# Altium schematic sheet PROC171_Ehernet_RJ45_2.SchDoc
size 431 x 279 mm; Date: Not shown in title block; ApprovedBy: Not shown in title block; CheckedBy: Not shown in title block; Author: Not shown in title block; CompanyName: Not shown in title block; Engineer: Not shown in title block; Organization: Not shown in title block; Address1: Not shown in title block; Address2: Not shown in title block; Address3: Not shown in title block; Address4: Not shown in title block; DocumentNumber: 20; Revision: Use project parameter SCH_Rev; SheetNumber: 20; SheetTotal: 27; PageSetup: Record=PageOptions¦CenterHorizontal=True¦CenterVertical=True¦PrintScale=1.00¦XCorrection=1.00¦YCorrection=1.00¦PrintKind=0¦BorderSize=5000000¦LeftOffset=0¦BottomOffset=0¦Orientation=2¦PaperLength=1000¦PaperWidth=1000¦Scale=100¦PaperSource=15¦PrintQuality=600¦MediaType=1¦DitherType=10¦PaperKind=Letter¦PrintScaleMode=1
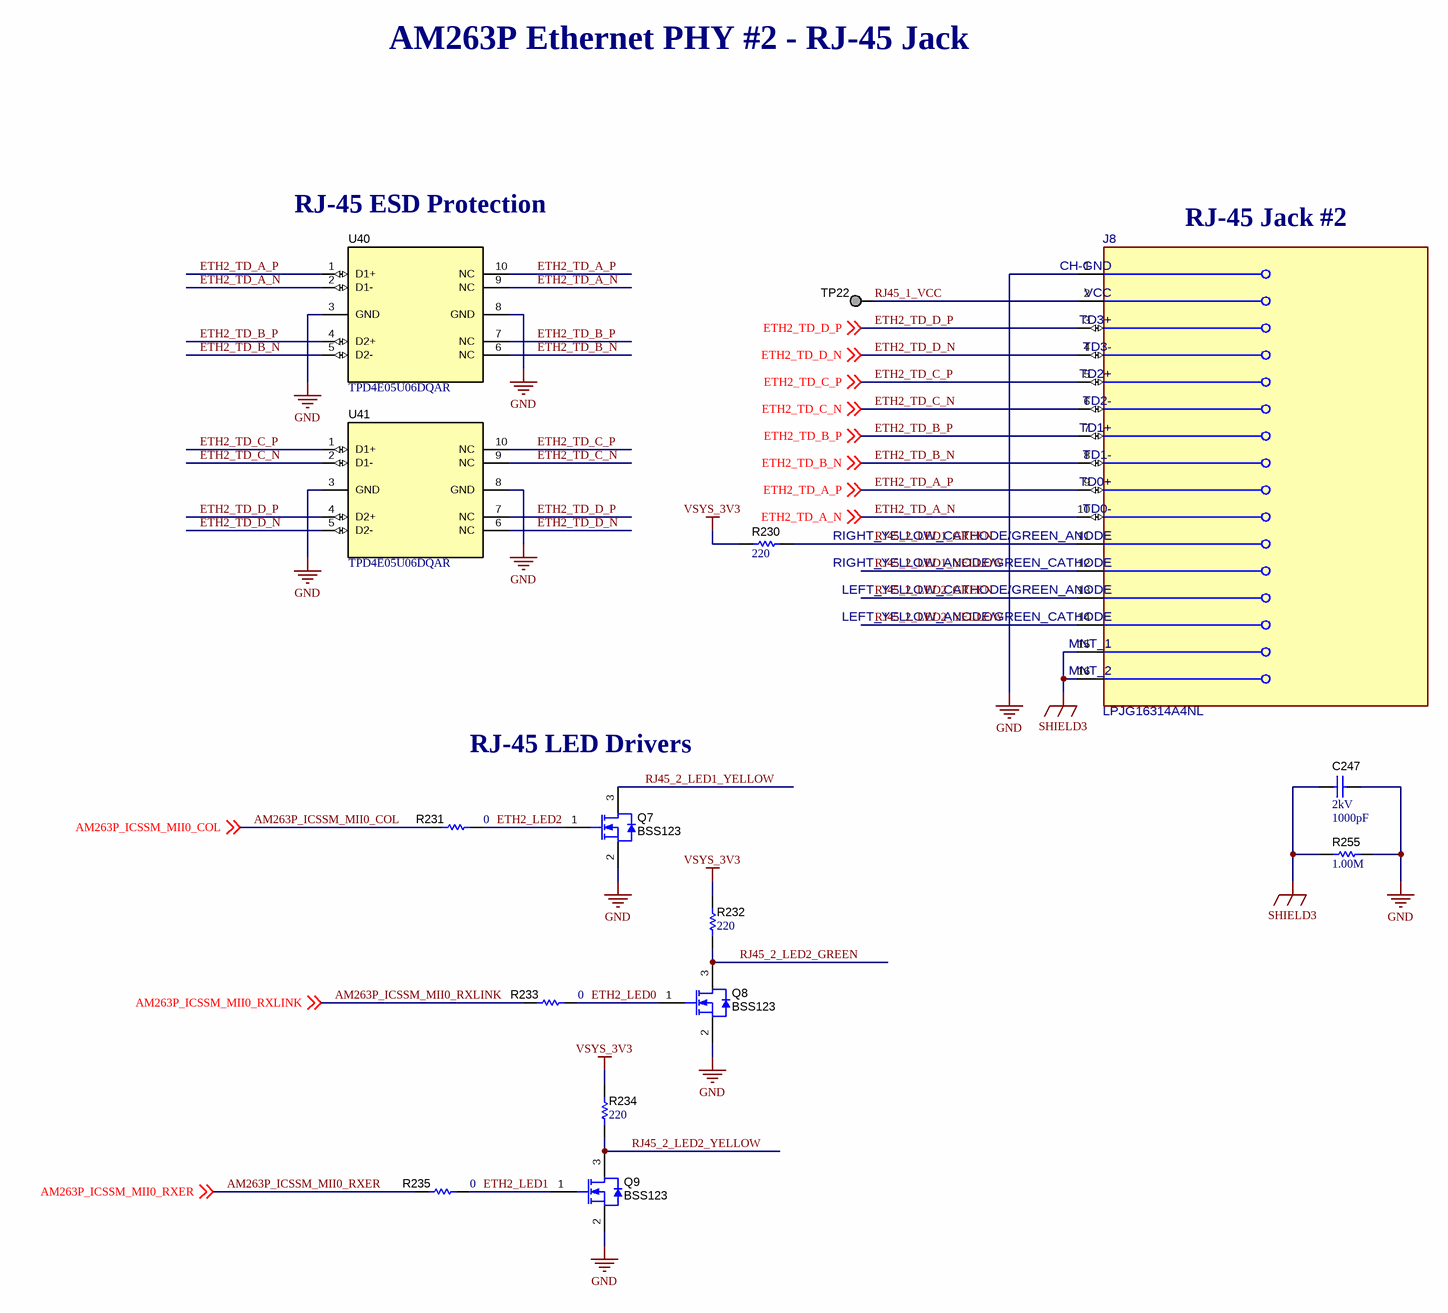
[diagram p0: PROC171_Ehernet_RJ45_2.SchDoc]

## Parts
C247  VDC_V: 2kV  ValueDisplayed: 1000pF  [1808]  (hidden comment: GR442QR73D102KW01L)
J8  LPJG16314A4NL  [FP-LPJG16314A4NL_CONN_RJ45-MFG]
Q7  BSS123  [SOT-23]
Q8  BSS123  [SOT-23]
Q9  BSS123  [SOT-23]
R230  ValueDisplayed: 220  [0402]  (hidden comment: CRCW0402220RJNED)
R231  ValueDisplayed: 0  [0402L]  (hidden comment: ERJ-2GE0R00X)
R232  ValueDisplayed: 220  [0402]  (hidden comment: CRCW0402220RJNED)
R233  ValueDisplayed: 0  [0402L]  (hidden comment: ERJ-2GE0R00X)
R234  ValueDisplayed: 220  [0402]  (hidden comment: CRCW0402220RJNED)
R235  ValueDisplayed: 0  [0402L]  (hidden comment: ERJ-2GE0R00X)
R255  ValueDisplayed: 1.00M  [0805_HV]  (hidden comment: ERJ-6ENF1004V)
TP22  TESTPOINT  [TP_25MIL-SMT]  (value not drawn)  (no BOM)
U40  TPD4E05U06DQAR  [DQA0010A]
U41  TPD4E05U06DQAR  [DQA0010A]

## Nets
GND: C247.1 J8.1(CH-GND) Q7.2(S) Q8.2(S) Q9.2(S) R255.2 U40.3(GND) U40.8(GND) U41.3(GND) U41.8(GND)
SHIELD3: C247.2 J8.15(MNT_1) J8.16(MNT_2) R255.1
VSYS_3V3: R230.1 R232.2 R234.2
AM263P_ICSSM_MII0_COL: R231.2 ; off-sheet AM263P_ICSSM_MII0_COL
AM263P_ICSSM_MII0_RXER: R235.2 ; off-sheet AM263P_ICSSM_MII0_RXER
AM263P_ICSSM_MII0_RXLINK: R233.2 ; off-sheet AM263P_ICSSM_MII0_RXLINK
ETH2_LED0: Q8.1(G) R233.1
ETH2_LED1: Q9.1(G) R235.1
ETH2_LED2: Q7.1(G) R231.1
ETH2_TD_A_N: J8.10(TD0-) U40.2(D1-) U40.9(NC) ; off-sheet ETH2_TD_A_N
ETH2_TD_A_P: J8.9(TD0+) U40.1(D1+) U40.10(NC) ; off-sheet ETH2_TD_A_P
ETH2_TD_B_N: J8.8(TD1-) U40.5(D2-) U40.6(NC) ; off-sheet ETH2_TD_B_N
ETH2_TD_B_P: J8.7(TD1+) U40.4(D2+) U40.7(NC) ; off-sheet ETH2_TD_B_P
ETH2_TD_C_N: J8.6(TD2-) U41.2(D1-) U41.9(NC) ; off-sheet ETH2_TD_C_N
ETH2_TD_C_P: J8.5(TD2+) U41.1(D1+) U41.10(NC) ; off-sheet ETH2_TD_C_P
ETH2_TD_D_N: J8.4(TD3-) U41.5(D2-) U41.6(NC) ; off-sheet ETH2_TD_D_N
ETH2_TD_D_P: J8.3(TD3+) U41.4(D2+) U41.7(NC) ; off-sheet ETH2_TD_D_P
RJ45_1_VCC: J8.2(VCC) TP22.1
RJ45_2_LED1_GREEN: J8.11(RIGHT_YELLOW_CATHODE/GREEN_ANODE) R230.2
RJ45_2_LED1_YELLOW: J8.12(RIGHT_YELLOW_ANODE/GREEN_CATHODE) Q7.3(D)
RJ45_2_LED2_GREEN: J8.13(LEFT_YELLOW_CATHODE/GREEN_ANODE) Q8.3(D) R232.1
RJ45_2_LED2_YELLOW: J8.14(LEFT_YELLOW_ANODE/GREEN_CATHODE) Q9.3(D) R234.1

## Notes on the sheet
- AM263P Ethernet PHY #2 - RJ-45 Jack
- RJ-45 ESD Protection
- RJ-45 Jack #2
- RJ-45 LED Drivers

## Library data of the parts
C247 = CMP-0009436-2: CAP, CERM, 1000 pF, 2000 V, +/- 10%, X7R, 1808; Manufacturer: MuRata; TaMin_C: -55°C; Polarized: N; SizeAreaWB_mm2: 16.5; Value1: Unknown; U/M: EA; Value: 1000pF; TaMax_C: 125°C; SizeZ_mm: 2.03; SizeX_mm: 4.5; SizeY_mm: 2; Value2: 2000V; SizeArea_mm2: 9; Cap_F: 1nF; AEC Category: Q200
J8 = CMP-0093483-1: RJ45 Connector with 1000 Base-TX Inetgrated Magnetic; Manufacturer: Link-PP; SizeZ_mm: 13.7mm; AEC Qualified: No; DUT-Pitch_mm: 1.27mm; Conn Gender: Female; Is Female: yes; ContactFinish: Gold; Conn Orientation: Horizontal
Q7-Q9 = CMP-0000947-2: MOSFET, N-CH, 100 V, 0.17 A, SOT-23; Alternate Manufacturer: None; Manufacturer: Fairchild Semiconductor; SizeZ_mm: 1.1; ChType: N; Value2: 1.8 nC; Value1: 1; VdsMax_V: 100V; SizeX_mm: 2.5; SizeY_mm: 3; Vgs_V: 20V; Value: 100V; Rdson45_ohm: 10; SizeArea_mm2: 7.5; AEC Category: Q101; IdsMax_A: 1.7dA; SizeAreaWB_mm2: 14; U/M: EA; QgTyp_nC: 1.8
R230 R232 R234 = CMP-0026878-3: RES, 220, 5%, 0.063 W, AEC-Q200 Grade 0, 0402; Manufacturer: Vishay-Dale; Power_W: 63mW; TempCo: 200 ppm/C; Value_Code: 220R; Value: 220; EIA_Code: E24; SizeX_mm: 1; SizeY_mm: 0.5; SizeZ_mm: 0.6; Value2: 0.063W; AEC Qualified: Y; VDC_V: 50V; AEC Category: Q200; AEC Grade: 0
R231 R233 R235 = CMP-0026992-3: RES, 0, 5%, 0.1 W, AEC-Q200 Grade 0, 0402; Manufacturer: Panasonic; Power_W: 100mW; TempCo: 600 ppm/C; Value_Code: 0000; Value: 0; EIA_Code: E24; SizeX_mm: 1; SizeY_mm: 0.5; SizeZ_mm: 0.6; Value2: 0.1W; AEC Qualified: Y; VDC_V: 50V; AEC Category: Q200; SizeAreaWB_mm2: 3
R255 = CMP-0021522-3: RES, 1.00 M, 1%, 0.125 W, AEC-Q200 Grade 0, 0805; Manufacturer: Panasonic; Power_W: 125mW; TempCo: 100 ppm/C; Value_Code: 1M00; Value: 1.00Meg; EIA_Code: E96; Res_ohm: 1M; SizeX_mm: 2; SizeY_mm: 1.25; SizeZ_mm: 1.45; Value2: 0.125W; SizeArea_mm2: 2.5; AEC Qualified: Y; AEC Category: Q200; AEC Grade: 0; SizeAreaWB_mm2: 6.75
TP22 = CMP-0078143-3: TEST POINT.  No entry in BOM.
U40 U41 = CMP-0073613-3: 4-Channel Ultra-Low-Capacitance IEC ESD Protection Diode, DQA0010A (USON-10); Alternate Manufacturer: Texas Instruments; Green_Lifecycle: Active; SizeAreaWB_mm2: 7.0; Green_REACh: Passed; SizeZ_mm: 0.55; SizeX_mm: 1.0; SizeY_mm: 2.5; CompType: IC; AEC Category: Q200; AEC Qualified: N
